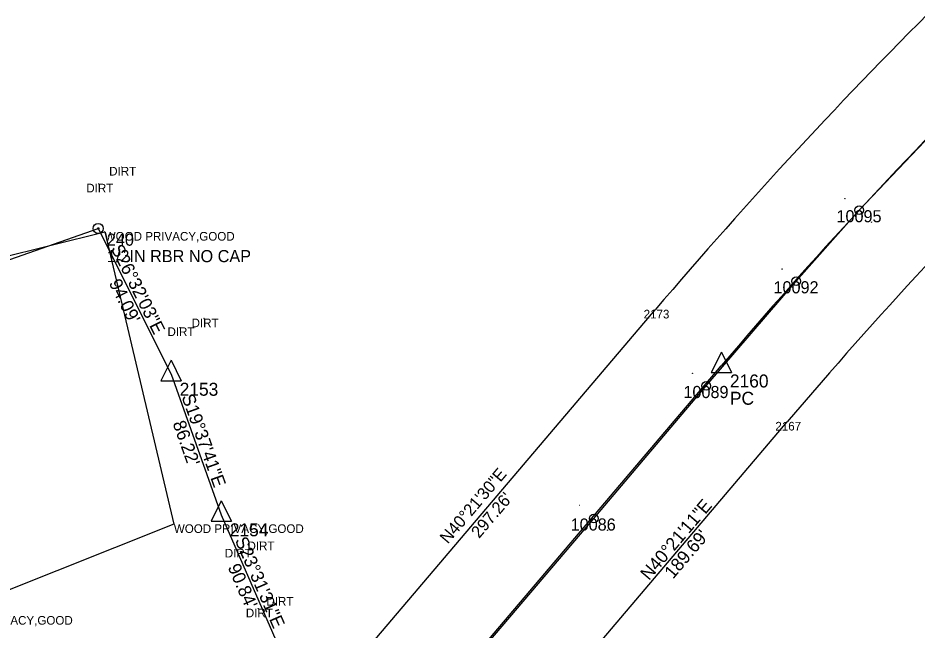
# Model space of a CAD drawing. Extents: x 1431802 to 1457777, y 1852108 to 1876350.
# Drawn here: x 1443925 to 1444444, y 1855196 to 1855549 of the extents above; entities that cross this region are included whole.
import ezdxf

# ---------------------------------------------------------------- set-up
doc = ezdxf.new("R2010")
doc.units = 0
for name, color, linetype in [('S_CAL_CORNER', 7, 'Continuous'), ('S_CAL_CORNER_ANNOT', 7, 'Continuous'), ('S_DRIVEWAY_ANNOT', 7, 'Continuous'), ('S_EXIST_ROW', 7, 'Continuous'), ('S_EXIST_ROW_ANNOT', 7, 'Continuous'), ('S_EXISTING_ALIGNMENT', 7, 'Continuous'), ('S_EXISTING_ALIGNMENT_ANNOT', 7, 'Continuous'), ('S_FENCE', 7, 'Continuous'), ('S_FENCE_ANNOT', 7, 'Continuous'), ('S_IRON_PIN', 7, 'Continuous'), ('S_IRON_PIN_ANNOT', 7, 'Continuous'), ('S_MSC_PT_SYM', 7, 'Continuous'), ('S_PROPERTY', 7, 'Continuous'), ('S_PROPERTY_ANNOT', 7, 'Continuous'), ('S_RDW_PT_SYM', 7, 'Continuous')]:
    doc.layers.add(name, color=color, linetype=linetype)

msp = doc.modelspace()

# ---------------------------------------------------------------- linework, layer by layer
at = {"layer": 'S_CAL_CORNER'}
for p, q in [((1444331.28, 1855356.15), (1444325.4, 1855344.33)), ((1444331.28, 1855356.15), (1444337.09, 1855344.33)), ((1444013.5, 1855351.37), (1444007.62, 1855339.55)), ((1444013.5, 1855351.37), (1444019.31, 1855339.55)), ((1444325.4, 1855344.33), (1444337.09, 1855344.33)), ((1444007.62, 1855339.55), (1444019.31, 1855339.55)), ((1444042.46, 1855270.16), (1444036.58, 1855258.34)), ((1444042.46, 1855270.16), (1444048.27, 1855258.34)), ((1444036.58, 1855258.34), (1444048.27, 1855258.34))]:
    msp.add_line(p, q, dxfattribs=at)
at = {"layer": 'S_EXIST_ROW'}
for p, q in [((1444100.59, 1855154.03), (1444293.09, 1855380.54)), ((1444246.47, 1855171.24), (1444369.29, 1855315.79))]:
    msp.add_line(p, q, dxfattribs=at)
for radius, end in [(2914.79, 139.6489), (2814.79, 139.64902)]:
    msp.add_arc((1446514.42, 1853493.3), radius, 129.89896, end, dxfattribs=at)
at = {"layer": 'S_EXISTING_ALIGNMENT'}
for p, q in [((1444410.85, 1855438.11), (1444474, 1855504.74)), ((1444374.48, 1855397.05), (1444410.85, 1855438.11)), ((1444322.49, 1855336.55), (1444374.48, 1855397.05)), ((1443986.7, 1854942.69), (1444331.19, 1855348.17)), ((1444257.52, 1855260), (1444322.49, 1855336.55)), ((1444192.52, 1855183.54), (1444257.52, 1855260))]:
    msp.add_line(p, q, dxfattribs=at)
for centre in [(1444410.85, 1855438.11), (1444374.48, 1855397.05), (1444322.49, 1855336.55), (1444257.52, 1855260)]:
    msp.add_circle(centre, 2.5, dxfattribs=at)
msp.add_arc((1446514.42, 1853493.3), 2864.79, 129.89896, 139.64896, dxfattribs=at)
at = {"layer": 'S_FENCE'}
for p, q in [((1443835.31, 1855390.91), (1443975.13, 1855425.51)), ((1443975.13, 1855425.51), (1444015.05, 1855256.61)), ((1444015.05, 1855256.61), (1443881.63, 1855203.62))]:
    msp.add_line(p, q, dxfattribs=at)
at = {"layer": 'S_IRON_PIN'}
for radius in [2.91, 0.411, 0.262, 0.212, 0.145, 0.0822, 0.0581]:
    msp.add_circle((1443971.37, 1855427.57), radius, dxfattribs=at)
at = {"layer": 'S_MSC_PT_SYM'}
for points in [[(1443975.13, 1855425.51), (1443975.13, 1855425.56), (1443975.13, 1855425.51), (1443975.08, 1855425.51), (1443975.13, 1855425.51), (1443975.13, 1855425.46), (1443975.13, 1855425.51), (1443975.18, 1855425.51)], [(1444015.05, 1855256.61), (1444015.05, 1855256.66), (1444015.05, 1855256.61), (1444015, 1855256.61), (1444015.05, 1855256.61), (1444015.05, 1855256.56), (1444015.05, 1855256.61), (1444015.1, 1855256.61)]]:
    msp.add_lwpolyline(points, dxfattribs=at)
at = {"layer": 'S_PROPERTY'}
for p, q in [((1443761.35, 1855354.04), (1443971.37, 1855427.57)), ((1443971.37, 1855427.57), (1444013.41, 1855343.39)), ((1444013.41, 1855343.39), (1444042.37, 1855262.18)), ((1444042.37, 1855262.18), (1444078.63, 1855178.89))]:
    msp.add_line(p, q, dxfattribs=at)
at = {"layer": 'S_RDW_PT_SYM'}
for points in [[(1443984.91, 1855463.13), (1443984.91, 1855463.18), (1443984.91, 1855463.13), (1443984.86, 1855463.13), (1443984.91, 1855463.13), (1443984.91, 1855463.08), (1443984.91, 1855463.13), (1443984.96, 1855463.13)], [(1443971.68, 1855453.37), (1443971.68, 1855453.42), (1443971.68, 1855453.37), (1443971.63, 1855453.37), (1443971.68, 1855453.37), (1443971.68, 1855453.32), (1443971.68, 1855453.37), (1443971.73, 1855453.37)], [(1444402.62, 1855444.79), (1444402.62, 1855444.83), (1444402.62, 1855444.79), (1444402.57, 1855444.79), (1444402.62, 1855444.79), (1444402.62, 1855444.73), (1444402.62, 1855444.79), (1444402.67, 1855444.79)], [(1444418.04, 1855431.27), (1444418.04, 1855431.32), (1444418.04, 1855431.27), (1444417.99, 1855431.27), (1444418.04, 1855431.27), (1444418.04, 1855431.22), (1444418.04, 1855431.27), (1444418.09, 1855431.27)], [(1444366.32, 1855404.1), (1444366.32, 1855404.15), (1444366.32, 1855404.1), (1444366.27, 1855404.1), (1444366.32, 1855404.1), (1444366.32, 1855404.05), (1444366.32, 1855404.1), (1444366.37, 1855404.1)], [(1444382.19, 1855389.98), (1444382.19, 1855390.03), (1444382.19, 1855389.98), (1444382.14, 1855389.98), (1444382.19, 1855389.98), (1444382.19, 1855389.93), (1444382.19, 1855389.98), (1444382.24, 1855389.98)], [(1444032.48, 1855375.47), (1444032.48, 1855375.52), (1444032.48, 1855375.47), (1444032.43, 1855375.47), (1444032.48, 1855375.47), (1444032.48, 1855375.42), (1444032.48, 1855375.47), (1444032.53, 1855375.47)], [(1444018.57, 1855370.38), (1444018.57, 1855370.43), (1444018.57, 1855370.38), (1444018.52, 1855370.38), (1444018.57, 1855370.38), (1444018.57, 1855370.33), (1444018.57, 1855370.38), (1444018.62, 1855370.38)], [(1444314.65, 1855343.84), (1444314.65, 1855343.89), (1444314.65, 1855343.84), (1444314.6, 1855343.84), (1444314.65, 1855343.84), (1444314.65, 1855343.79), (1444314.65, 1855343.84), (1444314.7, 1855343.84)], [(1444330.73, 1855330.23), (1444330.73, 1855330.28), (1444330.73, 1855330.23), (1444330.68, 1855330.23), (1444330.73, 1855330.23), (1444330.73, 1855330.18), (1444330.73, 1855330.23), (1444330.78, 1855330.23)], [(1444249.41, 1855267.68), (1444249.41, 1855267.73), (1444249.41, 1855267.68), (1444249.36, 1855267.68), (1444249.41, 1855267.68), (1444249.41, 1855267.63), (1444249.41, 1855267.68), (1444249.46, 1855267.68)], [(1444265.43, 1855253.15), (1444265.43, 1855253.2), (1444265.43, 1855253.15), (1444265.38, 1855253.15), (1444265.43, 1855253.15), (1444265.43, 1855253.1), (1444265.43, 1855253.15), (1444265.48, 1855253.15)], [(1444064.77, 1855246.66), (1444064.77, 1855246.71), (1444064.77, 1855246.66), (1444064.72, 1855246.66), (1444064.77, 1855246.66), (1444064.77, 1855246.61), (1444064.77, 1855246.66), (1444064.82, 1855246.66)], [(1444051.66, 1855242.44), (1444051.66, 1855242.49), (1444051.66, 1855242.44), (1444051.61, 1855242.44), (1444051.66, 1855242.44), (1444051.66, 1855242.39), (1444051.66, 1855242.44), (1444051.71, 1855242.44)], [(1444075.71, 1855214.63), (1444075.71, 1855214.68), (1444075.71, 1855214.63), (1444075.66, 1855214.63), (1444075.71, 1855214.63), (1444075.71, 1855214.58), (1444075.71, 1855214.63), (1444075.76, 1855214.63)], [(1444063.82, 1855207.91), (1444063.82, 1855207.96), (1444063.82, 1855207.91), (1444063.77, 1855207.91), (1444063.82, 1855207.91), (1444063.82, 1855207.86), (1444063.82, 1855207.91), (1444063.87, 1855207.91)]]:
    msp.add_lwpolyline(points, dxfattribs=at)

# ---------------------------------------------------------------- texts
at = {"layer": 'S_CAL_CORNER_ANNOT'}
for s, p in [('2160', (1444336.19, 1855335.67)), ('2153', (1444018.41, 1855330.89)), ('PC', (1444336.19, 1855325.67)), ('2154', (1444047.37, 1855249.68))]:
    msp.add_text(s, height=7.5, dxfattribs=at).set_placement(p)
at = {"layer": 'S_DRIVEWAY_ANNOT'}
for p in [(1443977.72, 1855458.13), (1443964.49, 1855448.37), (1444025.29, 1855370.47), (1444011.38, 1855365.38), (1444057.58, 1855241.66), (1444044.47, 1855237.44), (1444068.52, 1855209.63), (1444056.63, 1855202.91)]:
    msp.add_text('DIRT', height=5, dxfattribs=at).set_placement(p)
at = {"layer": 'S_EXIST_ROW_ANNOT'}
for s, p in [('2173', (1444286.36, 1855375.54)), ('2167', (1444362.44, 1855310.79))]:
    msp.add_text(s, height=5, dxfattribs=at).set_placement(p)
for s, p in [('N40%%d21\'30"E', (1444173.3, 1855244.9)), ("297.26'", (1444191.39, 1855248.12))]:
    msp.add_text(s, height=7, rotation=49.6417, dxfattribs=at).set_placement(p)
at = {"layer": 'S_EXISTING_ALIGNMENT_ANNOT'}
for s, p in [('10095', (1444397.73, 1855431.11)), ('10092', (1444361.36, 1855390.05)), ('10089', (1444309.35, 1855329.55)), ('10086', (1444244.21, 1855253))]:
    msp.add_text(s, height=7, dxfattribs=at).set_placement(p)
at = {"layer": 'S_FENCE_ANNOT'}
for p in [(1443975.13, 1855420.51), (1444015.05, 1855251.61), (1443881.63, 1855198.62)]:
    msp.add_text('WOOD PRIVACY,GOOD', height=5, dxfattribs=at).set_placement(p)
at = {"layer": 'S_IRON_PIN_ANNOT'}
for s, p in [('240', (1443976.38, 1855417.57)), ('1/2IN RBR NO CAP', (1443976.38, 1855408.07))]:
    msp.add_text(s, height=7, dxfattribs=at).set_placement(p)
at = {"layer": 'S_PROPERTY_ANNOT'}
for s, rotation, p in [('S26%%d32\'03"E', 296.5341, (1443978.52, 1855416.05)), ("94.09'", 296.5341, (1443977.33, 1855396.05)), ('S19%%d37\'41"E', 289.628, (1444019.39, 1855330.35)), ("86.22'", 289.628, (1444014.25, 1855314.98)), ('N40%%d21\'11"E', 49.6468, (1444289.46, 1855223.76)), ('S23%%d31\'31"E', 293.5253, (1444050.14, 1855247.46)), ("189.69'", 49.6468, (1444303.35, 1855224.66)), ("90.84'", 293.5253, (1444046.02, 1855231.88))]:
    msp.add_text(s, height=7.5, rotation=rotation, dxfattribs=at).set_placement(p)

doc.saveas('drawing.dxf')
